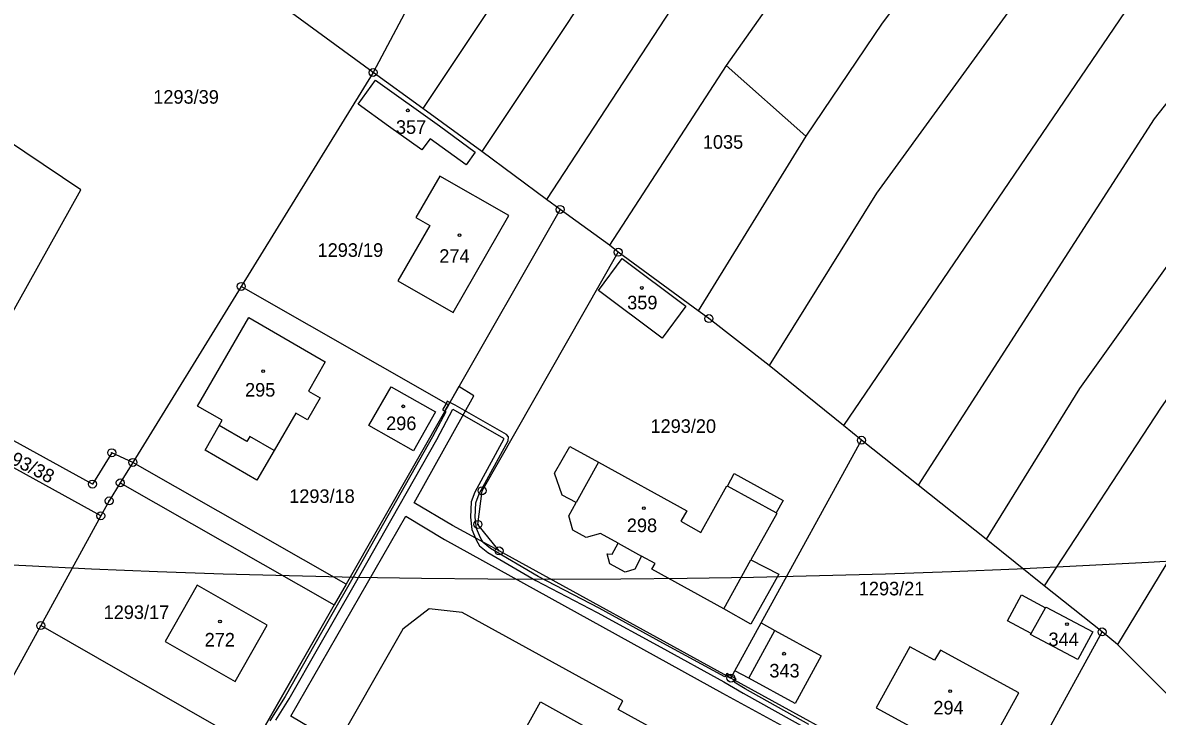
# Model space of a CAD drawing. Extents: x -680203 to -673936, y -1102717 to -1093650.
# Drawn here: x -676484.3 to -676342.1, y -1100705.8 to -1100618.9 of the extents above; entities that cross this region are included whole.
import ezdxf

# ---------------------------------------------------------------- set-up
doc = ezdxf.new("R2010")
doc.units = 0
for name, color, linetype in [('_Ideová část', 7, 'Continuous'), ('SOxx02xx_Koleje_param další_Popis10', 7, 'Continuous'), ('SOxxxxxx_Koleje_LN_parametry_Popis10', 7, 'Continuous'), ('SOxxxxxx_Koleje_param další_Popis10', 7, 'Continuous'), ('SOxxxxxx_Osa_bod_P', 7, 'Continuous'), ('SOxxxxxx_Staničení_Popis10', 7, 'Continuous'), ('x_prac', 7, 'Continuous')]:
    doc.layers.add(name, color=color, linetype=linetype)

msp = doc.modelspace()

# ---------------------------------------------------------------- linework, layer by layer
at = {"layer": '_Ideová část'}
msp.add_circle((-676417.7, -1099401.52), 1287.12, dxfattribs=at)
at = {"layer": 'SOxx02xx_Koleje_param další_Popis10'}
for centre, radius in [((-676440.43, -1100625.1), 0.5), ((-676440.43, -1100625.1), 0.0303), ((-676416.99, -1100642.27), 0.5), ((-676416.99, -1100642.27), 0.0303), ((-676409.69, -1100647.63), 0.5), ((-676409.69, -1100647.63), 0.0303), ((-676456.94, -1100651.91), 0.5), ((-676456.94, -1100651.91), 0.0303), ((-676398.33, -1100655.95), 0.5), ((-676398.33, -1100655.95), 0.0303), ((-676379.22, -1100671.2), 0.5), ((-676379.22, -1100671.2), 0.0303), ((-676473.17, -1100672.77), 0.5), ((-676473.17, -1100672.77), 0.0303), ((-676470.53, -1100673.98), 0.5), ((-676470.53, -1100673.98), 0.0303), ((-676475.59, -1100676.69), 0.5), ((-676475.59, -1100676.69), 0.0303), ((-676472.11, -1100676.54), 0.5), ((-676472.11, -1100676.54), 0.0303), ((-676473.5, -1100678.8), 0.5), ((-676426.76, -1100677.53), 0.5), ((-676426.76, -1100677.53), 0.0303), ((-676473.5, -1100678.8), 0.0303), ((-676474.55, -1100680.68), 0.5), ((-676474.55, -1100680.68), 0.0303), ((-676427.28, -1100681.75), 0.5), ((-676427.28, -1100681.75), 0.0303), ((-676424.63, -1100685.08), 0.5), ((-676424.63, -1100685.08), 0.0303), ((-676482.08, -1100694.44), 0.5), ((-676482.08, -1100694.44), 0.0303), ((-676349.07, -1100695.24), 0.5), ((-676349.07, -1100695.24), 0.0303), ((-676395.58, -1100701.02), 0.5), ((-676395.58, -1100701.02), 0.0303)]:
    msp.add_circle(centre, radius, dxfattribs=at)
at = {"layer": 'SOxxxxxx_Koleje_LN_parametry_Popis10'}
for points in [[(-676375.31, -1100712.14), (-676395.58, -1100701.02), (-676424.63, -1100685.08), (-676430.48, -1100681.91), (-676435.28, -1100679.03), (-676427.8, -1100665.65), (-676429.66, -1100664.46), (-676430.97, -1100666.75), (-676443.81, -1100689.23), (-676445.3, -1100691.84), (-676455.47, -1100709.64)], [(-676385.8, -1100706.84), (-676393.78, -1100702.38), (-676395.19, -1100701.55), (-676395.05, -1100701.31), (-676394.93, -1100701.1), (-676395.46, -1100700.81), (-676395.58, -1100701.02), (-676396.23, -1100700.67), (-676396.34, -1100700.88), (-676404.1, -1100696.64), (-676412.08, -1100692.26), (-676419.72, -1100688.28), (-676425.72, -1100684.76), (-676426.62, -1100684.04), (-676426.98, -1100683.42), (-676427.46, -1100682.25), (-676427.63, -1100680.83), (-676427.55, -1100679.05), (-676427.15, -1100677.94), (-676423.51, -1100671.27), (-676423.46, -1100670.79), (-676423.7, -1100670.49), (-676430.12, -1100666.79), (-676430.81, -1100666.46), (-676430.97, -1100666.75), (-676431.44, -1100667.57), (-676431.31, -1100667.64), (-676432.97, -1100670.79), (-676438.56, -1100680.67), (-676443.28, -1100689.03), (-676447.73, -1100696.76), (-676451.45, -1100703.32), (-676453.36, -1100706.38)], [(-676452.61, -1100706.3), (-676450.93, -1100703.62), (-676447.24, -1100697.11), (-676442.78, -1100689.35), (-676438.04, -1100680.97), (-676432.45, -1100671.09), (-676430.45, -1100667.29), (-676424.08, -1100670.96), (-676424.09, -1100671.09), (-676427.69, -1100677.7), (-676428.15, -1100678.93), (-676428.23, -1100680.85), (-676428.04, -1100682.41)], [(-676444.9, -1100709.28), (-676450.74, -1100705.81), (-676436.32, -1100680.74), (-676431.48, -1100683.65), (-676396.63, -1100702.9), (-676380.07, -1100711.93)], [(-676428.04, -1100682.41), (-676427.52, -1100683.68), (-676427.08, -1100684.44), (-676426.06, -1100685.26), (-676420.04, -1100688.8), (-676412.36, -1100692.79), (-676404.38, -1100697.16), (-676396.45, -1100701.5), (-676394.06, -1100702.9), (-676386.1, -1100707.36), (-676378.44, -1100711.37), (-676373.18, -1100714.9), (-676369.76, -1100717.98), (-676368.05, -1100720.13), (-676366.84, -1100722.52), (-676366, -1100725.35), (-676365.49, -1100730.35)]]:
    msp.add_lwpolyline(points, dxfattribs=at)
for points in [[(-676431.27, -1100666.58), (-676431.74, -1100667.4), (-676431.44, -1100667.57), (-676430.97, -1100666.75)], [(-676431.27, -1100666.58), (-676430.97, -1100666.75), (-676430.81, -1100666.46), (-676431.12, -1100666.31)], [(-676396.11, -1100700.45), (-676396.23, -1100700.67), (-676395.58, -1100701.02), (-676395.46, -1100700.81)]]:
    msp.add_lwpolyline(points, close=True, dxfattribs=at)
at = {"layer": 'SOxxxxxx_Koleje_param další_Popis10'}
for centre in [(-676436.06, -1100629.85), (-676429.59, -1100645.48), (-676406.74, -1100652.11), (-676454.19, -1100662.54), (-676436.64, -1100666.95), (-676406.49, -1100679.71), (-676459.61, -1100693.93), (-676353.46, -1100694.26), (-676388.92, -1100697.96), (-676368.1, -1100702.65)]:
    msp.add_circle(centre, 0.175, dxfattribs=at)
at = {"layer": 'SOxxxxxx_Staničení_Popis10'}
for p, q in [((-676456.24, -1100671.36), (-676459.72, -1100669.34)), ((-676455.85, -1100670.72), (-676456.24, -1100671.36)), ((-676452.8, -1100672.49), (-676455.85, -1100670.72)), ((-676412.18, -1100673.95), (-676414.98, -1100679.02)), ((-676389.91, -1100680.32), (-676396.01, -1100676.95)), ((-676409.71, -1100684.12), (-676406.78, -1100685.73)), ((-676396.47, -1100692.33), (-676393.08, -1100686.19)), ((-676357.94, -1100695.43), (-676356.14, -1100692.21)), ((-676393.33, -1100701.04), (-676390.07, -1100695.05))]:
    msp.add_line(p, q, dxfattribs=at)
at = {"layer": 'x_prac'}
for p, q in [((-676440.43, -1100625.1), (-676459.53, -1100611.1)), ((-676396.17, -1100624.24), (-676410.78, -1100646.73)), ((-676386.17, -1100633.07), (-676396.17, -1100624.24)), ((-676440.43, -1100625.1), (-676456.94, -1100651.91)), ((-676434.2, -1100629.61), (-676440.43, -1100625.1)), ((-676426.81, -1100635.01), (-676434.2, -1100629.61)), ((-676386.17, -1100633.07), (-676399.67, -1100654.99)), ((-676418.67, -1100641.01), (-676426.81, -1100635.01)), ((-676416.99, -1100642.27), (-676418.67, -1100641.01)), ((-676416.99, -1100642.27), (-676430.97, -1100666.75)), ((-676410.78, -1100646.73), (-676416.99, -1100642.27)), ((-676409.69, -1100647.63), (-676410.78, -1100646.73)), ((-676426.76, -1100677.53), (-676409.69, -1100647.63)), ((-676399.67, -1100654.99), (-676409.69, -1100647.63)), ((-676456.94, -1100651.91), (-676470.53, -1100673.98)), ((-676430.97, -1100666.75), (-676456.94, -1100651.91)), ((-676381.48, -1100669.37), (-676390.79, -1100661.84)), ((-676430.97, -1100666.75), (-676443.81, -1100689.23)), ((-676475.59, -1100676.69), (-676492.41, -1100667.44)), ((-676329.15, -1100667.08), (-676347.13, -1100696.79)), ((-676379.22, -1100671.2), (-676381.48, -1100669.37)), ((-676474.55, -1100680.68), (-676493.89, -1100670.03)), ((-676391.79, -1100694.11), (-676379.22, -1100671.2)), ((-676372.12, -1100676.83), (-676379.22, -1100671.2)), ((-676473.17, -1100672.77), (-676475.59, -1100676.69)), ((-676470.53, -1100673.98), (-676473.17, -1100672.77)), ((-676470.53, -1100673.98), (-676472.11, -1100676.54)), ((-676443.81, -1100689.23), (-676470.53, -1100673.98)), ((-676472.11, -1100676.54), (-676445.3, -1100691.84)), ((-676363.58, -1100683.62), (-676372.12, -1100676.83)), ((-676474.55, -1100680.68), (-676482.08, -1100694.44)), ((-676356.32, -1100689.47), (-676363.58, -1100683.62)), ((-676349.07, -1100695.24), (-676356.32, -1100689.47)), ((-676445.3, -1100691.84), (-676455.47, -1100709.64)), ((-676482.08, -1100694.44), (-676487.64, -1100704.57)), ((-676455.47, -1100709.64), (-676482.08, -1100694.44)), ((-676395.07, -1100700.09), (-676391.79, -1100694.11)), ((-676360.78, -1100716.59), (-676349.07, -1100695.24)), ((-676347.13, -1100696.79), (-676349.07, -1100695.24)), ((-676336.45, -1100707.51), (-676347.13, -1100696.79)), ((-676395.58, -1100701.02), (-676395.07, -1100700.09))]:
    msp.add_line(p, q, dxfattribs=at)
for points in [[(-676296.41, -1100435.24), (-676352.19, -1100498.76), (-676394.63, -1100552.94), (-676428.31, -1100602.24), (-676440.43, -1100625.1)], [(-676289.24, -1100442.35), (-676320.47, -1100477.7), (-676383.66, -1100557.27), (-676406.15, -1100587.52), (-676434.2, -1100629.61)], [(-676282.89, -1100448.46), (-676329.47, -1100502.42), (-676354.84, -1100534.53), (-676381.89, -1100569.8), (-676398.54, -1100591.62), (-676404.68, -1100601.78), (-676426.81, -1100635.01)], [(-676274.86, -1100454.28), (-676327.82, -1100515.73), (-676358.65, -1100554.96), (-676379.56, -1100583.35), (-676397.19, -1100608.1), (-676418.67, -1100641.01)], [(-676267.51, -1100460.64), (-676307.6, -1100507.49), (-676333.38, -1100538.78), (-676362.09, -1100575.88), (-676396.17, -1100624.24)], [(-676257.19, -1100470.33), (-676300.07, -1100518.18), (-676312.83, -1100533.84), (-676376.63, -1100618.9), (-676386.17, -1100633.07)], [(-676248.98, -1100478.46), (-676291.8, -1100528.58), (-676319.21, -1100562.15), (-676342.4, -1100592.14), (-676377.34, -1100640.22), (-676390.79, -1100661.84)], [(-676240.58, -1100486.73), (-676278.14, -1100530.87), (-676316.99, -1100577.95), (-676344.12, -1100614.41), (-676381.48, -1100669.37)], [(-676233.08, -1100494.38), (-676261.63, -1100528.3), (-676342.52, -1100630.92), (-676372.12, -1100676.83)], [(-676225.13, -1100501.56), (-676255.52, -1100536.68), (-676307.92, -1100603.74), (-676319.26, -1100619), (-676351.91, -1100664.71), (-676363.58, -1100683.62)], [(-676218.29, -1100507.59), (-676243.54, -1100538.33), (-676261.98, -1100560.46), (-676301.86, -1100610.26), (-676341.67, -1100667.04), (-676356.32, -1100689.47)], [(-676490.26, -1100663.4), (-676477.04, -1100639.79), (-676495.86, -1100627.2)], [(-676442.29, -1100629.08), (-676440.13, -1100626.08), (-676432.12, -1100631.8), (-676427.62, -1100635.09), (-676428.76, -1100636.67), (-676433.25, -1100633.43), (-676434.3, -1100634.8), (-676438.48, -1100631.81), (-676442.29, -1100629.08)], [(-676423.4, -1100643.03), (-676432.06, -1100638.08), (-676435.06, -1100643.28), (-676433.33, -1100644.27), (-676437.32, -1100651.21), (-676430.39, -1100655.2), (-676423.4, -1100643.03)], [(-676412.19, -1100652.41), (-676409.21, -1100648.4), (-676401.21, -1100654.4), (-676404.21, -1100658.4), (-676412.19, -1100652.41)], [(-676390.79, -1100661.84), (-676398.33, -1100655.95), (-676399.67, -1100654.99)], [(-676452.8, -1100672.49), (-676455, -1100676.2), (-676461.47, -1100672.45), (-676459.72, -1100669.34), (-676459.35, -1100668.69), (-676462.41, -1100666.93), (-676456.01, -1100655.83), (-676446.41, -1100661.36), (-676448.51, -1100665.03), (-676447.04, -1100665.87), (-676448.63, -1100668.66), (-676450.11, -1100667.82), (-676452.8, -1100672.49)], [(-676438.17, -1100664.49), (-676432.6, -1100667.66), (-676435.37, -1100672.53), (-676440.95, -1100669.36), (-676438.17, -1100664.49)], [(-676405.47, -1100687.38), (-676405.08, -1100686.66), (-676406.78, -1100685.73), (-676407.62, -1100687.38), (-676408.84, -1100687.74), (-676410.76, -1100686.68), (-676411.09, -1100685.46), (-676410.47, -1100685.5), (-676409.71, -1100684.12), (-676411.93, -1100682.9), (-676413.73, -1100683.38), (-676415.4, -1100682.46), (-676415.9, -1100680.68), (-676414.98, -1100679.02), (-676416.71, -1100678.09), (-676417.68, -1100675.35), (-676415.77, -1100671.99), (-676412.18, -1100673.95), (-676401.12, -1100680.04), (-676401.85, -1100681.36), (-676399.33, -1100682.75), (-676396.11, -1100676.9), (-676396.01, -1100676.95), (-676395.17, -1100675.38), (-676389.04, -1100678.77), (-676389.91, -1100680.32), (-676389.81, -1100680.37), (-676393.08, -1100686.19), (-676389.59, -1100687.99), (-676393.07, -1100694.25), (-676396.47, -1100692.33), (-676405.47, -1100687.38)], [(-676472.11, -1100676.54), (-676473.5, -1100678.8), (-676474.55, -1100680.68)], [(-676395.58, -1100701.02), (-676424.63, -1100685.08), (-676427.28, -1100681.75), (-676426.76, -1100677.53)], [(-676457.72, -1100701.44), (-676453.68, -1100694.39), (-676462.48, -1100689.38), (-676466.48, -1100696.42), (-676457.72, -1100701.44)], [(-676352.09, -1100698.71), (-676358.02, -1100695.57), (-676357.94, -1100695.43), (-676360.91, -1100693.84), (-676359.17, -1100690.6), (-676356.14, -1100692.21), (-676356.09, -1100692.12), (-676350.22, -1100695.23), (-676352.09, -1100698.71)], [(-676400.51, -1100710.01), (-676409.72, -1100704.96), (-676409.12, -1100703.86), (-676429.26, -1100692.81), (-676433.4, -1100692.34), (-676436.68, -1100694.9), (-676445.91, -1100711.05)], [(-676391.79, -1100694.11), (-676390.07, -1100695.05), (-676384.26, -1100698.25), (-676387.53, -1100704.2), (-676393.33, -1100701.04), (-676395.07, -1100700.09)], [(-676377.36, -1100704.74), (-676364.42, -1100711.81), (-676359.51, -1100702.86), (-676369.32, -1100697.51), (-676370.05, -1100698.78), (-676373.15, -1100697.12), (-676377.36, -1100704.74)], [(-676366.96, -1100720.05), (-676370.56, -1100715.47), (-676375.31, -1100712.14), (-676395.58, -1100701.02)], [(-676408.41, -1100710.99), (-676412.28, -1100718.01), (-676415.79, -1100716.07), (-676416.17, -1100716.74), (-676424.07, -1100712.37), (-676419.45, -1100704.01), (-676411.54, -1100708.39), (-676411.89, -1100709.05), (-676408.41, -1100710.99)]]:
    msp.add_lwpolyline(points, dxfattribs=at)

# ---------------------------------------------------------------- texts
at = {"layer": 'SOxxxxxx_Osa_bod_P'}
for s, p in [('1293/39', (-676467.97, -1100629.01)), ('357', (-676437.56, -1100632.79)), ('1035', (-676399.1, -1100634.66)), ('1293/19', (-676447.38, -1100648.21)), ('274', (-676432.13, -1100648.96)), ('359', (-676408.58, -1100654.79)), ('295', (-676456.47, -1100665.73)), ('296', (-676438.79, -1100669.93)), ('1293/20', (-676405.66, -1100670.28)), ('1293/18', (-676450.94, -1100679.06)), ('298', (-676408.62, -1100682.72)), ('1293/21', (-676379.55, -1100690.65)), ('1293/17', (-676474.19, -1100693.61)), ('272', (-676461.53, -1100697.06)), ('344', (-676355.78, -1100697.01)), ('343', (-676390.76, -1100700.94)), ('294', (-676370.21, -1100705.58))]:
    msp.add_text(s, height=1.7, dxfattribs=at).set_placement(p)
msp.add_text('1293/38', height=1.7, rotation=333, dxfattribs=at).set_placement((-676488.25, -1100672.93))

doc.saveas('drawing.dxf')
